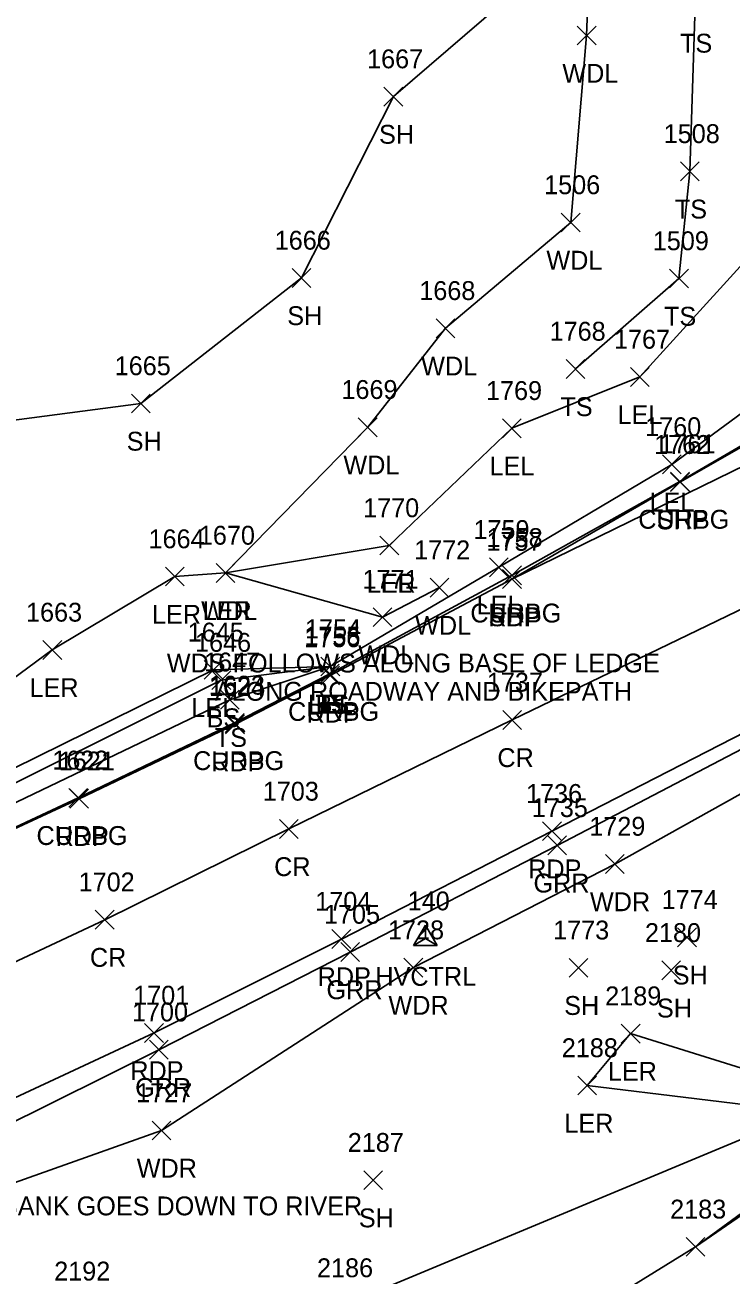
# Model space of a CAD drawing. Extents: x 1638344 to 1639591, y 610835 to 612202.
# Drawn here: x 1638532 to 1638606.9, y 611608.8 to 611741.3 of the extents above; entities that cross this region are included whole.
import ezdxf

# ---------------------------------------------------------------- set-up
doc = ezdxf.new("R2010")
doc.units = 0
for name, color, linetype in [('C_A', 7, 'Continuous'), ('C_I', 7, 'Continuous'), ('CPSM', 7, 'Continuous'), ('L_A', 7, 'Continuous'), ('L_C', 7, 'Continuous'), ('L_I', 7, 'Continuous'), ('L_TIC', 7, 'Continuous'), ('LARO', 7, 'Continuous'), ('LAWA', 7, 'Continuous'), ('LAWE', 7, 'Continuous'), ('LELB', 7, 'Continuous'), ('LSOGP', 7, 'Continuous'), ('P_A', 7, 'Continuous'), ('P_I', 7, 'Continuous'), ('P_TIC', 7, 'Continuous'), ('PET', 7, 'Continuous'), ('PRC', 7, 'Continuous'), ('PSP', 7, 'Continuous'), ('R_A', 7, 'Continuous'), ('R_I', 7, 'Continuous'), ('R_TIC', 7, 'Continuous'), ('RC', 7, 'Continuous'), ('RGR', 7, 'Continuous')]:
    doc.layers.add(name, color=color, linetype=linetype)

msp = doc.modelspace()

# ---------------------------------------------------------------- linework, layer by layer
at = {"layer": 'CPSM'}
for p, q in [((1638573.25, 611643.72), (1638574.5, 611645.89)), ((1638575.75, 611643.72), (1638574.5, 611645.89)), ((1638574.5, 611644.45), (1638574.5, 611645.89)), ((1638573.25, 611643.72), (1638574.5, 611644.45)), ((1638573.25, 611643.72), (1638575.75, 611643.72)), ((1638574.5, 611644.45), (1638574.5, 611644.45)), ((1638574.5, 611644.45), (1638575.75, 611643.72))]:
    msp.add_line(p, q, dxfattribs=at)
at = {"layer": 'L_TIC'}
for points in [[(1638590.61, 611739.2), (1638592.61, 611741.2)], [(1638592.61, 611739.2), (1638590.61, 611741.2)], [(1638570.1, 611732.73), (1638572.1, 611734.73)], [(1638572.1, 611732.73), (1638570.1, 611734.73)], [(1638601.56, 611724.8), (1638603.56, 611726.8)], [(1638603.56, 611724.8), (1638601.56, 611726.8)], [(1638588.92, 611719.38), (1638590.92, 611721.38)], [(1638590.92, 611719.38), (1638588.92, 611721.38)], [(1638560.35, 611713.5), (1638562.35, 611715.5)], [(1638562.35, 611713.5), (1638560.35, 611715.5)], [(1638600.41, 611713.44), (1638602.41, 611715.44)], [(1638602.41, 611713.44), (1638600.41, 611715.44)], [(1638600.41, 611713.44), (1638602.41, 611715.44)], [(1638602.41, 611713.44), (1638600.41, 611715.44)], [(1638575.63, 611708.16), (1638577.63, 611710.16)], [(1638577.63, 611708.16), (1638575.63, 611710.16)], [(1638589.42, 611703.85), (1638591.42, 611705.85)], [(1638591.42, 611703.85), (1638589.42, 611705.85)], [(1638596.25, 611703), (1638598.25, 611705)], [(1638598.25, 611703), (1638596.25, 611705)], [(1638543.31, 611700.19), (1638545.31, 611702.19)], [(1638545.31, 611700.19), (1638543.31, 611702.19)], [(1638567.38, 611697.67), (1638569.38, 611699.67)], [(1638569.38, 611697.67), (1638567.38, 611699.67)], [(1638582.67, 611697.56), (1638584.67, 611699.56)], [(1638584.67, 611697.56), (1638582.67, 611699.56)], [(1638599.65, 611693.73), (1638601.65, 611695.73)], [(1638601.65, 611693.73), (1638599.65, 611695.73)], [(1638569.67, 611685.13), (1638571.67, 611687.13)], [(1638571.67, 611685.13), (1638569.67, 611687.13)], [(1638569.67, 611685.13), (1638571.67, 611687.13)], [(1638571.67, 611685.13), (1638569.67, 611687.13)], [(1638581.3, 611682.82), (1638583.3, 611684.82)], [(1638583.3, 611682.82), (1638581.3, 611684.82)], [(1638546.91, 611681.84), (1638548.91, 611683.84)], [(1638548.91, 611681.84), (1638546.91, 611683.84)], [(1638552.29, 611682.22), (1638554.29, 611684.22)], [(1638554.29, 611682.22), (1638552.29, 611684.22)], [(1638552.29, 611682.22), (1638554.29, 611684.22)], [(1638554.29, 611682.22), (1638552.29, 611684.22)], [(1638574.99, 611680.67), (1638576.99, 611682.67)], [(1638576.99, 611680.67), (1638574.99, 611682.67)], [(1638568.95, 611677.54), (1638570.95, 611679.54)], [(1638570.95, 611677.54), (1638568.95, 611679.54)], [(1638533.91, 611674.06), (1638535.91, 611676.06)], [(1638535.91, 611674.06), (1638533.91, 611676.06)], [(1638563.41, 611672.3), (1638565.41, 611674.3)], [(1638565.41, 611672.3), (1638563.41, 611674.3)], [(1638563.41, 611672.3), (1638565.41, 611674.3)], [(1638565.41, 611672.3), (1638563.41, 611674.3)], [(1638563.41, 611672.3), (1638565.41, 611674.3)], [(1638565.41, 611672.3), (1638563.41, 611674.3)], [(1638551.02, 611671.95), (1638553.02, 611673.95)], [(1638553.02, 611671.95), (1638551.02, 611673.95)], [(1638551.84, 611670.86), (1638553.84, 611672.86)], [(1638553.84, 611670.86), (1638551.84, 611672.86)], [(1638552.75, 611668.78), (1638554.75, 611670.78)], [(1638554.75, 611668.78), (1638552.75, 611670.78)], [(1638593.6, 611651.36), (1638595.6, 611653.36)], [(1638595.6, 611651.36), (1638593.6, 611653.36)], [(1638601.26, 611643.59), (1638603.26, 611645.59)], [(1638603.26, 611643.59), (1638601.26, 611645.59)], [(1638572.22, 611640.38), (1638574.22, 611642.38)], [(1638574.22, 611640.38), (1638572.22, 611642.38)], [(1638589.74, 611640.36), (1638591.74, 611642.36)], [(1638591.74, 611640.36), (1638589.74, 611642.36)], [(1638599.58, 611640.09), (1638601.58, 611642.09)], [(1638601.58, 611640.09), (1638599.58, 611642.09)], [(1638595.28, 611633.38), (1638597.28, 611635.38)], [(1638597.28, 611633.38), (1638595.28, 611635.38)], [(1638590.67, 611627.88), (1638592.67, 611629.88)], [(1638592.67, 611627.88), (1638590.67, 611629.88)], [(1638545.5, 611623.11), (1638547.5, 611625.11)], [(1638547.5, 611623.11), (1638545.5, 611625.11)], [(1638567.95, 611617.84), (1638569.95, 611619.84)], [(1638569.95, 611617.84), (1638567.95, 611619.84)], [(1638602.16, 611610.77), (1638604.16, 611612.77)], [(1638604.16, 611610.77), (1638602.16, 611612.77)]]:
    msp.add_lwpolyline(points, dxfattribs=at)
at = {"layer": 'LARO'}
for points in [[(1638616.65, 611755.78), (1638613.18, 611751.32), (1638612.17, 611743.21), (1638612.86, 611730.74), (1638612.87, 611721.16), (1638597.25, 611704), (1638583.67, 611698.56), (1638570.67, 611686.13)], [(1638507.5, 611686.1), (1638504.66, 611675.82), (1638500.03, 611663.35), (1638503.63, 611660.7), (1638501.69, 611656.36), (1638496.94, 611651.9), (1638492.23, 611644.24), (1638496.15, 611644.86), (1638498.52, 611643.9), (1638500.15, 611645.64), (1638505.84, 611650.22), (1638522.65, 611658.49), (1638552.02, 611672.95), (1638564.41, 611673.3), (1638582.3, 611683.82), (1638600.65, 611694.73), (1638614.45, 611704.87)], [(1638525.15, 611698.68), (1638523.45, 611690.12), (1638517.04, 611687.19), (1638512.88, 611675.3), (1638508.29, 611660.49), (1638523.73, 611666.85), (1638534.91, 611675.06), (1638547.91, 611682.84), (1638553.29, 611683.22), (1638570.67, 611686.13)], [(1638620.52, 611645.81), (1638614.95, 611626.06), (1638591.67, 611628.88), (1638596.28, 611634.38), (1638613.13, 611629.12)]]:
    msp.add_lwpolyline(points, dxfattribs=at)
at = {"layer": 'LAWA'}
for points in [[(1638592.06, 611751.78), (1638591.61, 611740.2), (1638589.92, 611720.38), (1638576.63, 611709.16), (1638568.38, 611698.67), (1638553.29, 611683.22), (1638569.95, 611678.54), (1638575.99, 611681.67)], [(1638355.93, 611578.15), (1638379.62, 611581.44), (1638409.5, 611585.94), (1638444.06, 611588.57), (1638475.66, 611594.37), (1638498.86, 611601.36), (1638508.25, 611607.89), (1638527.03, 611617.21), (1638546.5, 611624.11), (1638573.22, 611641.38), (1638594.6, 611652.36), (1638613.43, 611662.84), (1638623.73, 611665.86), (1638642.74, 611667.09)]]:
    msp.add_lwpolyline(points, dxfattribs=at)
at = {"layer": 'LAWE'}
msp.add_lwpolyline([(1638639.67, 611638.46), (1638603.16, 611611.77), (1638574.66, 611594.16), (1638565.4, 611585.15), (1638539.63, 611574.58)], dxfattribs=at)
at = {"layer": 'LELB'}
for points in [[(1638603.11, 611743.39), (1638602.56, 611725.8), (1638601.41, 611714.44)], [(1638601.41, 611714.44), (1638590.42, 611704.85)], [(1638500.15, 611645.64), (1638506.45, 611647.85), (1638523.32, 611655.19), (1638553.75, 611669.78), (1638564.41, 611673.3)], [(1638506.28, 611648.95), (1638522.97, 611656.98), (1638552.84, 611671.86), (1638564.41, 611673.3)], [(1638614.95, 611626.06), (1638565.75, 611605.55)]]:
    msp.add_lwpolyline(points, dxfattribs=at)
at = {"layer": 'LSOGP'}
for points in [[(1638592.06, 611751.78), (1638571.1, 611733.73), (1638561.35, 611714.5), (1638544.31, 611701.19), (1638525.15, 611698.68)], [(1638574.66, 611594.16), (1638603.16, 611611.77), (1638639.76, 611636.95), (1638645.69, 611635.64), (1638652.33, 611625.89), (1638655.05, 611620.55), (1638662.57, 611614.01), (1638668.61, 611607.24)]]:
    msp.add_lwpolyline(points, dxfattribs=at)
at = {"layer": 'P_TIC'}
for points in [[(1638600.51, 611691.84), (1638602.51, 611693.84)], [(1638602.51, 611691.84), (1638600.51, 611693.84)], [(1638582.68, 611681.57), (1638584.68, 611683.57)], [(1638584.68, 611681.57), (1638582.68, 611683.57)], [(1638582.68, 611681.57), (1638584.68, 611683.57)], [(1638584.68, 611681.57), (1638582.68, 611683.57)], [(1638582.68, 611681.57), (1638584.68, 611683.57)], [(1638584.68, 611681.57), (1638582.68, 611683.57)], [(1638563.39, 611671.35), (1638565.39, 611673.35)], [(1638565.39, 611671.35), (1638563.39, 611673.35)], [(1638553.29, 611666.17), (1638555.29, 611668.17)], [(1638555.29, 611666.17), (1638553.29, 611668.17)], [(1638582.71, 611666.64), (1638584.71, 611668.64)], [(1638584.71, 611666.64), (1638582.71, 611668.64)], [(1638536.76, 611658.28), (1638538.76, 611660.28)], [(1638538.76, 611658.28), (1638536.76, 611660.28)], [(1638559.01, 611655.08), (1638561.01, 611657.08)], [(1638561.01, 611655.08), (1638559.01, 611657.08)], [(1638586.93, 611654.84), (1638588.93, 611656.84)], [(1638588.93, 611654.84), (1638586.93, 611656.84)], [(1638539.47, 611645.46), (1638541.47, 611647.46)], [(1638541.47, 611645.46), (1638539.47, 611647.46)], [(1638564.58, 611643.41), (1638566.58, 611645.41)], [(1638566.58, 611643.41), (1638564.58, 611645.41)], [(1638544.7, 611633.45), (1638546.7, 611635.45)], [(1638546.7, 611633.45), (1638544.7, 611635.45)]]:
    msp.add_lwpolyline(points, dxfattribs=at)
at = {"layer": 'PET'}
for points in [[(1638356.39, 611589.51), (1638387.53, 611591.22), (1638422.64, 611595.34), (1638450.6, 611600.07), (1638477.61, 611605.87), (1638499.25, 611614.17), (1638522.41, 611623.62), (1638545.7, 611634.45), (1638565.58, 611644.41), (1638587.93, 611655.84), (1638616.74, 611670.62), (1638633.38, 611678.5), (1638639.77, 611680.79), (1638643.67, 611682.22), (1638643.83, 611693.96), (1638643.72, 611707.5), (1638631.78, 611704.69), (1638616.32, 611698.49), (1638583.68, 611682.57)], [(1638355.97, 611616.93), (1638384.54, 611618.59), (1638398.86, 611619.61), (1638400.74, 611618.43), (1638405.64, 611618.57), (1638407.82, 611620.3), (1638423.28, 611621.83), (1638446.81, 611626.11), (1638452.75, 611627.38), (1638459.03, 611628.7), (1638481.78, 611635.47), (1638483.49, 611635.84), (1638487.22, 611637.22), (1638500.05, 611642.23), (1638515.48, 611648.95), (1638537.76, 611659.28), (1638554.29, 611667.17), (1638564.39, 611672.35), (1638583.68, 611682.57)]]:
    msp.add_lwpolyline(points, dxfattribs=at)
at = {"layer": 'PRC'}
msp.add_lwpolyline([(1638356.12, 611602.69), (1638388.66, 611605), (1638420.62, 611608.46), (1638449.14, 611613.12), (1638473.93, 611619.15), (1638495.39, 611626.42), (1638517.33, 611635.58), (1638540.47, 611646.46), (1638560.01, 611656.08), (1638583.71, 611667.64), (1638612.7, 611681.66), (1638628.79, 611688.73), (1638636.08, 611691.34), (1638643.83, 611693.96)], dxfattribs=at)
at = {"layer": 'PSP'}
msp.add_lwpolyline([(1638583.68, 611682.57), (1638601.51, 611692.84), (1638615.25, 611700.69), (1638623.05, 611705.27)], dxfattribs=at)
at = {"layer": 'R_TIC'}
for points in [[(1638600.51, 611691.91), (1638602.51, 611693.91)], [(1638602.51, 611691.91), (1638600.51, 611693.91)], [(1638582.69, 611681.97), (1638584.69, 611683.97)], [(1638584.69, 611681.97), (1638582.69, 611683.97)], [(1638563.35, 611671.54), (1638565.35, 611673.54)], [(1638565.35, 611671.54), (1638563.35, 611673.54)], [(1638553.26, 611666.32), (1638555.26, 611668.32)], [(1638555.26, 611666.32), (1638553.26, 611668.32)], [(1638536.65, 611658.38), (1638538.65, 611660.38)], [(1638538.65, 611658.38), (1638536.65, 611660.38)], [(1638587.48, 611653.34), (1638589.48, 611655.34)], [(1638589.48, 611653.34), (1638587.48, 611655.34)], [(1638565.51, 611642.03), (1638567.51, 611644.03)], [(1638567.51, 611642.03), (1638565.51, 611644.03)], [(1638545.21, 611631.67), (1638547.21, 611633.67)], [(1638547.21, 611631.67), (1638545.21, 611633.67)]]:
    msp.add_lwpolyline(points, dxfattribs=at)
at = {"layer": 'RC'}
msp.add_lwpolyline([(1638483.44, 611635.97), (1638487.21, 611637.4), (1638499.85, 611642.34), (1638515.39, 611649), (1638537.65, 611659.38), (1638554.26, 611667.32), (1638564.35, 611672.54), (1638583.69, 611682.97), (1638601.51, 611692.91), (1638615.14, 611700.88), (1638623.05, 611705.27)], dxfattribs=at)
at = {"layer": 'RGR'}
msp.add_lwpolyline([(1638356.81, 611587.46), (1638387.61, 611589.77), (1638422.62, 611593.65), (1638451.31, 611597.61), (1638478.22, 611602.62), (1638500.77, 611610.66), (1638523.68, 611621.48), (1638546.21, 611632.67), (1638566.51, 611643.03), (1638588.48, 611654.34), (1638617.53, 611669.47), (1638633.84, 611677.48), (1638639.91, 611680.2), (1638642.7, 611681.41)], dxfattribs=at)

# ---------------------------------------------------------------- texts
at = {"layer": 'C_A'}
msp.add_text('HVCTRL', height=2, dxfattribs=at).set_placement((1638569.19, 611639.45))
at = {"layer": 'C_I'}
msp.add_text('140', height=2, dxfattribs=at).set_placement((1638572.62, 611647.45))
at = {"layer": 'L_A'}
for s, p in [('TS', (1638601.52, 611738.39)), ('WDL', (1638589.03, 611735.2)), ('SH', (1638569.58, 611728.73)), ('TS', (1638600.97, 611720.8)), ('WDL', (1638587.34, 611715.38)), ('SH', (1638559.84, 611709.5)), ('TS', (1638599.82, 611709.44)), ('TS', (1638599.82, 611709.44)), ('WDL', (1638574.05, 611704.16)), ('TS', (1638588.83, 611699.85)), ('LEL', (1638594.89, 611699)), ('SH', (1638542.8, 611696.19)), ('WDL', (1638565.8, 611693.67)), ('LEL', (1638581.31, 611693.56)), ('LEL', (1638598.28, 611689.73)), ('LER', (1638568.25, 611681.13)), ('LEL', (1638568.31, 611681.13)), ('LER', (1638545.49, 611677.84)), ('WDL', (1638550.7, 611678.22)), ('LER', (1638550.87, 611678.22)), ('LEL', (1638579.94, 611678.82)), ('WDL', (1638573.41, 611676.67)), ('WDL', (1638567.37, 611673.54)), ('LER', (1638532.49, 611670.06)), ('LEL', (1638562.05, 611668.3)), ('TS', (1638562.82, 611668.3)), ('BS', (1638562.85, 611668.3)), ('LEL', (1638549.66, 611667.95)), ('BS', (1638551.28, 611666.86)), ('TS', (1638552.15, 611664.78)), ('WDR', (1638591.96, 611647.36)), ('SH', (1638600.75, 611639.59)), ('WDR', (1638570.58, 611636.38)), ('SH', (1638589.23, 611636.36)), ('SH', (1638599.07, 611636.09)), ('LER', (1638593.86, 611629.38)), ('LER', (1638589.25, 611623.88)), ('WDR', (1638543.87, 611619.11)), ('SH', (1638567.44, 611613.84))]:
    msp.add_text(s, height=2, dxfattribs=at).set_placement(p)
at = {"layer": 'L_C'}
for s, p in [('WDS FOLLOWS ALONG BASE OF LEDGE', (1638547.06, 611672.67)), ('ALONG ROADWAY AND BIKEPATH', (1638552.15, 611669.67)), ('STEEP BANK GOES DOWN TO RIVER', (1638519.95, 611615.11))]:
    msp.add_text(s, height=2, dxfattribs=at).set_placement(p)
at = {"layer": 'L_I'}
for s, p in [('1667', (1638568.31, 611736.73)), ('1508', (1638599.79, 611728.8)), ('1506', (1638587.1, 611723.38)), ('1666', (1638558.51, 611717.5)), ('1509', (1638598.63, 611717.44)), ('1509', (1638598.63, 611717.44)), ('1668', (1638573.85, 611712.16)), ('1768', (1638587.68, 611707.85)), ('1767', (1638594.51, 611707)), ('1665', (1638541.53, 611704.19)), ('1669', (1638565.59, 611701.67)), ('1769', (1638580.93, 611701.56)), ('1760', (1638597.82, 611697.73)), ('1770', (1638567.89, 611689.13)), ('1770', (1638567.89, 611689.13)), ('1759', (1638579.6, 611686.82)), ('1664', (1638545.12, 611685.84)), ('1670', (1638550.46, 611686.22)), ('1670', (1638550.46, 611686.22)), ('1772', (1638573.3, 611684.67)), ('1771', (1638567.82, 611681.54)), ('1663', (1638532.12, 611678.06)), ('1754', (1638561.72, 611676.3)), ('1754', (1638561.72, 611676.3)), ('1754', (1638561.72, 611676.3)), ('1645', (1638549.28, 611675.95)), ('1646', (1638550.05, 611674.86)), ('1647', (1638551.01, 611672.78)), ('1729', (1638591.89, 611655.36)), ('1774', (1638599.57, 611647.59)), ('1728', (1638570.53, 611644.38)), ('1773', (1638588.05, 611644.36)), ('2180', (1638597.8, 611644.09)), ('2189', (1638593.58, 611637.38)), ('2188', (1638588.97, 611631.88)), ('1727', (1638543.81, 611627.11)), ('2187', (1638566.26, 611621.84)), ('2183', (1638600.47, 611614.77)), ('2192', (1638535.11, 611608.2)), ('2186', (1638563, 611608.55))]:
    msp.add_text(s, height=2, dxfattribs=at).set_placement(p)
at = {"layer": 'P_A'}
for s, p in [('SHP', (1638599.04, 611687.84)), ('SHP', (1638581.21, 611677.57)), ('RDP', (1638581.16, 611677.57)), ('RDP', (1638581.16, 611677.57)), ('RDP', (1638561.88, 611667.35)), ('RDP', (1638551.78, 611662.17)), ('CR', (1638582.14, 611662.64)), ('RDP', (1638535.25, 611654.28)), ('CR', (1638558.45, 611651.08)), ('RDP', (1638585.41, 611650.84)), ('CR', (1638538.9, 611641.46)), ('RDP', (1638563.07, 611639.41)), ('RDP', (1638543.19, 611629.45))]:
    msp.add_text(s, height=2, dxfattribs=at).set_placement(p)
at = {"layer": 'P_I'}
for s, p in [('1762', (1638598.77, 611695.84)), ('1757', (1638580.98, 611685.57)), ('1757', (1638580.98, 611685.57)), ('1757', (1638580.98, 611685.57)), ('1756', (1638561.64, 611675.35)), ('1624', (1638551.55, 611670.17)), ('1737', (1638581.02, 611670.64)), ('1621', (1638535.59, 611662.28)), ('1703', (1638557.24, 611659.08)), ('1736', (1638585.18, 611658.84)), ('1702', (1638537.7, 611649.46)), ('1704', (1638562.81, 611647.41)), ('1701', (1638543.49, 611637.45))]:
    msp.add_text(s, height=2, dxfattribs=at).set_placement(p)
at = {"layer": 'R_A'}
for s, p in [('CURBG', (1638597.09, 611687.91)), ('CURBG', (1638579.27, 611677.97)), ('CURBG', (1638559.93, 611667.54)), ('CURBG', (1638549.85, 611662.32)), ('CURBG', (1638533.23, 611654.38)), ('GRR', (1638585.97, 611649.34)), ('GRR', (1638564, 611638.03)), ('GRR', (1638543.7, 611627.67))]:
    msp.add_text(s, height=2, dxfattribs=at).set_placement(p)
at = {"layer": 'R_I'}
for s, p in [('1761', (1638599.33, 611695.91)), ('1758', (1638580.99, 611685.97)), ('1755', (1638561.66, 611675.54)), ('1623', (1638551.52, 611670.32)), ('1622', (1638534.91, 611662.38)), ('1735', (1638585.79, 611657.34)), ('1705', (1638563.74, 611646.03)), ('1700', (1638543.36, 611635.67))]:
    msp.add_text(s, height=2, dxfattribs=at).set_placement(p)

doc.saveas('drawing.dxf')
